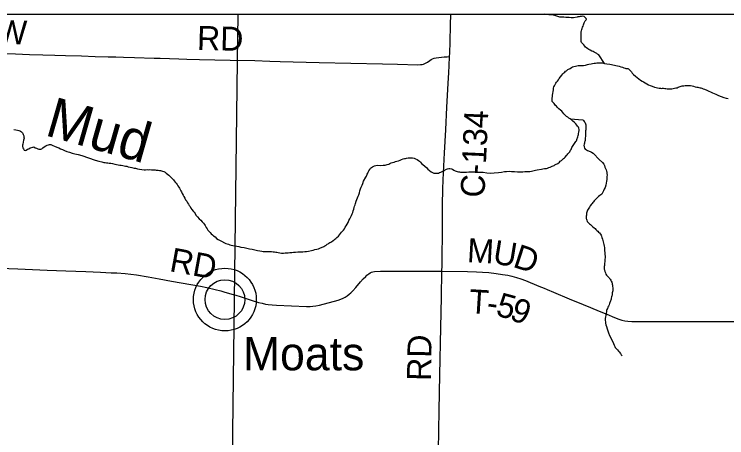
# Model space of a CAD drawing. Extents: x 2.1 to 73.9, y 4 to 26.
# Drawn here: x 44.65 to 45.494, y 24.403 to 24.905 of the extents above; entities that cross this region are included whole.
import ezdxf

# ---------------------------------------------------------------- set-up
doc = ezdxf.new("R2010")
doc.units = 0
for name, color, linetype in [('GM_X_County_Road', 7, 'Continuous'), ('GM_X_County_Road_Text', 7, 'Continuous'), ('GM_X_Minor_River', 7, 'Continuous'), ('GM_X_Minor_River_Text', 7, 'Continuous'), ('GM_X_Rail_Line', 7, 'Continuous'), ('GM_X_Township_Road', 7, 'Continuous'), ('GM_X_Township_Road_Text', 7, 'Continuous'), ('GM_X_Unincorporated', 7, 'Continuous'), ('GM_X_Unincorporated_Location', 7, 'Continuous'), ('GM_X_Unincorporated_Text', 7, 'Continuous'), ('SH_Data', 7, 'Continuous')]:
    doc.layers.add(name, color=color, linetype=linetype)

msp = doc.modelspace()

# ---------------------------------------------------------------- linework, layer by layer
at = {"layer": 'GM_X_County_Road'}
msp.add_line((45.16551, 24.84401), (45.16606, 24.85491), dxfattribs=at)
for points in [[(45.16606, 24.85491), (45.16626, 24.85886), (45.1666, 24.87222), (45.16722, 24.89212), (45.16754, 24.90511)], [(45.15687, 24.6007), (45.15704, 24.60732), (45.15719, 24.62068), (45.15741, 24.64213), (45.1576, 24.66451), (45.15768, 24.67881), (45.15796, 24.69807), (45.15826, 24.70846), (45.1589, 24.71731), (45.16008, 24.7409), (45.1615, 24.76822), (45.16283, 24.79492), (45.16439, 24.82285), (45.16511, 24.8362), (45.16551, 24.84401)], [(44.63313, 24.60432), (44.65487, 24.6033), (44.68929, 24.60188), (44.71164, 24.60095), (44.73522, 24.6001), (44.75263, 24.59946), (44.76535, 24.5988), (44.77187, 24.59851), (44.7818, 24.59776), (44.78831, 24.59704), (44.79508, 24.59605), (44.80888, 24.59374), (44.82205, 24.59143), (44.83673, 24.5888), (44.87101, 24.58265), (44.87863, 24.58106), (44.88827, 24.57875), (44.89496, 24.57715), (44.89999, 24.57584), (44.90984, 24.57298), (44.91268, 24.57211)], [(44.91268, 24.57211), (44.91788, 24.5705), (44.93107, 24.56625), (44.93965, 24.56359), (44.94384, 24.56248), (44.94806, 24.56154), (44.9511, 24.56105), (44.95571, 24.5606), (44.96097, 24.56029), (44.99668, 24.55882), (45.00068, 24.55887), (45.00407, 24.55908), (45.00774, 24.55956), (45.01199, 24.56037), (45.03384, 24.56632), (45.03733, 24.56755), (45.03988, 24.56862), (45.04233, 24.56989), (45.04465, 24.57137), (45.04708, 24.57323), (45.04915, 24.57507), (45.05131, 24.57726), (45.05479, 24.58122), (45.06046, 24.58782), (45.06381, 24.59152), (45.0666, 24.59446), (45.06797, 24.59578), (45.07023, 24.59747), (45.07183, 24.59852), (45.07356, 24.59937), (45.07509, 24.59988), (45.07698, 24.60022), (45.08417, 24.6006), (45.09413, 24.60064), (45.10656, 24.60053), (45.15687, 24.6007)], [(45.15193, 24.34944), (45.15216, 24.36148), (45.15276, 24.38821), (45.15376, 24.43545), (45.15451, 24.47771), (45.15565, 24.53366), (45.15644, 24.5697), (45.15687, 24.6007)]]:
    msp.add_lwpolyline(points, dxfattribs=at)
at = {"layer": 'GM_X_Minor_River'}
for points in [[(45.34948, 24.84681), (45.3426, 24.85718), (45.34129, 24.85796), (45.34016, 24.85874), (45.33884, 24.85952), (45.33714, 24.86031), (45.33582, 24.8609), (45.3343, 24.86149), (45.33261, 24.86247), (45.33072, 24.86345), (45.32959, 24.86423), (45.32809, 24.8652), (45.32696, 24.86617), (45.32603, 24.86732), (45.3251, 24.86867), (45.32417, 24.86982), (45.32229, 24.87156), (45.32193, 24.87271), (45.32195, 24.87404), (45.32178, 24.87556), (45.32181, 24.87746), (45.32165, 24.87918), (45.32168, 24.88107), (45.32171, 24.88316), (45.32173, 24.88449), (45.32213, 24.88563), (45.32253, 24.88695), (45.32293, 24.88809), (45.32333, 24.8896), (45.32412, 24.89111), (45.32471, 24.89243), (45.32511, 24.89375), (45.32551, 24.89489), (45.32572, 24.89583), (45.32669, 24.89715), (45.32746, 24.89808), (45.32824, 24.89902), (45.32787, 24.89998), (45.32656, 24.90133), (45.32525, 24.90249), (45.32373, 24.90289), (45.32221, 24.90254), (45.32068, 24.90237), (45.31935, 24.90201), (45.31801, 24.90185), (45.31687, 24.90148), (45.31267, 24.90098), (45.31134, 24.901), (45.30982, 24.90103), (45.30773, 24.90125), (45.30583, 24.90128), (45.30374, 24.90131), (45.30146, 24.90154), (45.29975, 24.90157), (45.29804, 24.90159), (45.29671, 24.9018), (45.29538, 24.90202), (45.29425, 24.90241), (45.29311, 24.90281), (45.29198, 24.90321), (45.29046, 24.90361), (45.28914, 24.90402), (45.28781, 24.90423), (45.28648, 24.90444), (45.28515, 24.90446), (45.28401, 24.90448), (45.28306, 24.90468), (45.28211, 24.90489), (45.28097, 24.9049), (45.28002, 24.90492), (45.27896, 24.90511)], [(45.30427, 24.83822), (45.306, 24.83952), (45.30696, 24.84007), (45.30792, 24.84044), (45.30888, 24.84099), (45.31022, 24.84192), (45.31156, 24.84266), (45.31328, 24.8432), (45.31519, 24.84355), (45.31672, 24.84391), (45.31844, 24.84426), (45.32053, 24.84423), (45.32262, 24.84439), (45.32472, 24.84454), (45.327, 24.84489), (45.32911, 24.84542), (45.33102, 24.84596), (45.33349, 24.8463), (45.33521, 24.84666), (45.33712, 24.84701), (45.33883, 24.84717), (45.34036, 24.84734), (45.34188, 24.84769), (45.34341, 24.84767), (45.34512, 24.84764), (45.34721, 24.84742), (45.34948, 24.84681), (45.35213, 24.8462), (45.35555, 24.84576), (45.35764, 24.84554), (45.36276, 24.84451), (45.36484, 24.84391), (45.36692, 24.84349), (45.36882, 24.84289), (45.37071, 24.84229), (45.37241, 24.8417), (45.37393, 24.84129), (45.37487, 24.8409), (45.37582, 24.84069), (45.37696, 24.84067), (45.3779, 24.84028), (45.37922, 24.83912), (45.38052, 24.83757), (45.38146, 24.8368), (45.38239, 24.83546), (45.38388, 24.83353), (45.38614, 24.83179), (45.3882, 24.83004), (45.39027, 24.82849), (45.39215, 24.82713), (45.39385, 24.82596), (45.39554, 24.8248), (45.39742, 24.82363), (45.3995, 24.82245), (45.40157, 24.82147), (45.40365, 24.82068), (45.40573, 24.81969), (45.40876, 24.8187), (45.41065, 24.81828), (45.41236, 24.81807), (45.41407, 24.81766), (45.41558, 24.81745), (45.41691, 24.81724), (45.41805, 24.81741), (45.4192, 24.81739), (45.42071, 24.81718), (45.42223, 24.81696), (45.42375, 24.81675), (45.42527, 24.81672), (45.42755, 24.81669), (45.42927, 24.81685), (45.43404, 24.81772), (45.43537, 24.81808), (45.43652, 24.81863), (45.43786, 24.81918), (45.43901, 24.81954), (45.44016, 24.81991), (45.44149, 24.82008), (45.4434, 24.82043), (45.44492, 24.82059), (45.44663, 24.82056), (45.44816, 24.82073), (45.44949, 24.82071), (45.4512, 24.82049), (45.4531, 24.82027), (45.45499, 24.81986), (45.45688, 24.81926), (45.45859, 24.81885), (45.45992, 24.81864), (45.46124, 24.81824), (45.46257, 24.81803), (45.46352, 24.81782), (45.46484, 24.81742), (45.46635, 24.81683), (45.46787, 24.81624), (45.46881, 24.81584), (45.46995, 24.81544), (45.47146, 24.81485), (45.47316, 24.81406), (45.47505, 24.81327), (45.47731, 24.8121)], [(45.26302, 24.71916), (45.26455, 24.71952), (45.26607, 24.71987), (45.26779, 24.72042), (45.26951, 24.72077), (45.27485, 24.72164), (45.27638, 24.72199), (45.27828, 24.72215), (45.28057, 24.7223), (45.2821, 24.72285), (45.28363, 24.7234), (45.28516, 24.72394), (45.2865, 24.72449), (45.28765, 24.72504), (45.28879, 24.7254), (45.28975, 24.72596), (45.29071, 24.72651), (45.29225, 24.72744), (45.29321, 24.7278), (45.29436, 24.72836), (45.29609, 24.72985), (45.29687, 24.73098), (45.29841, 24.7319), (45.29975, 24.73283), (45.30091, 24.73395), (45.30207, 24.73507), (45.30303, 24.73582), (45.30439, 24.7377), (45.30536, 24.73863), (45.30614, 24.73957), (45.30691, 24.74051), (45.30827, 24.7422), (45.30925, 24.74389), (45.30983, 24.74483), (45.31023, 24.74596), (45.31082, 24.74709), (45.3116, 24.74841), (45.31219, 24.74973), (45.31297, 24.75086), (45.31394, 24.75199), (45.31471, 24.75292), (45.31531, 24.75424), (45.31608, 24.75518), (45.31707, 24.75764), (45.31747, 24.75877), (45.31787, 24.7599), (45.31808, 24.76142), (45.31848, 24.76255), (45.31869, 24.76388), (45.31909, 24.76521), (45.31911, 24.76616), (45.31931, 24.7671), (45.31933, 24.76843), (45.31898, 24.77015), (45.31862, 24.77129), (45.31731, 24.77264), (45.31657, 24.7738), (45.31544, 24.77514), (45.31395, 24.77669), (45.31207, 24.77843), (45.31019, 24.77979), (45.30869, 24.78095), (45.30738, 24.78211), (45.30587, 24.78309), (45.30455, 24.78406), (45.30324, 24.78522), (45.3023, 24.78599), (45.30137, 24.78715), (45.30025, 24.7885), (45.29894, 24.79004), (45.29725, 24.79139), (45.29537, 24.79294), (45.29388, 24.79468), (45.29257, 24.79603), (45.29144, 24.797), (45.2907, 24.79815), (45.28977, 24.79949), (45.28865, 24.80046), (45.28753, 24.80181), (45.28754, 24.80295), (45.28737, 24.80409), (45.28802, 24.80902), (45.28824, 24.81111), (45.28847, 24.81358), (45.28889, 24.81566), (45.28911, 24.81756), (45.28951, 24.81907), (45.2901, 24.82039), (45.29089, 24.8219), (45.29167, 24.82322), (45.29264, 24.82453), (45.29361, 24.82584), (45.29478, 24.82754), (45.29594, 24.82904), (45.29731, 24.83111), (45.29905, 24.83279), (45.30021, 24.83448), (45.30137, 24.8356), (45.30234, 24.83654), (45.3033, 24.83747), (45.30427, 24.83822)], [(45.47731, 24.8121), (45.48128, 24.81032), (45.48449, 24.80894), (45.48751, 24.80756), (45.49073, 24.80637), (45.49357, 24.80576), (45.49584, 24.80515)], [(45.30869, 24.78095), (45.3237, 24.77995), (45.32464, 24.77918), (45.32538, 24.77803), (45.32632, 24.77706), (45.32686, 24.77534), (45.32722, 24.7742), (45.32739, 24.77305), (45.32737, 24.77172), (45.32732, 24.76811), (45.3271, 24.76679), (45.32708, 24.76527), (45.32706, 24.76375), (45.32704, 24.76242), (45.32681, 24.76014), (45.32659, 24.75844), (45.32657, 24.75673), (45.32635, 24.7554), (45.32596, 24.75427), (45.32575, 24.75332), (45.32555, 24.75237), (45.32533, 24.75104), (45.32512, 24.74972), (45.3253, 24.74877), (45.32528, 24.74782), (45.32583, 24.74629), (45.32658, 24.74532), (45.32808, 24.74435), (45.32921, 24.74376), (45.33035, 24.74336), (45.33129, 24.74297), (45.33262, 24.74238), (45.33413, 24.74178), (45.33582, 24.74062), (45.33713, 24.73946), (45.33825, 24.73811), (45.33938, 24.73695), (45.34012, 24.73599), (45.34162, 24.73463), (45.34312, 24.73309), (45.34725, 24.72941), (45.34874, 24.72749), (45.34928, 24.72577), (45.35001, 24.72405), (45.35075, 24.72214), (45.35129, 24.72061), (45.35184, 24.71927), (45.35202, 24.71832), (45.35238, 24.71736), (45.35236, 24.71622), (45.35253, 24.71451), (45.35231, 24.71299), (45.35229, 24.71128), (45.35207, 24.70939), (45.35165, 24.70711), (45.35123, 24.70484), (45.35082, 24.70257), (45.35021, 24.69992), (45.34922, 24.69765), (45.34843, 24.69595), (45.34764, 24.69426), (45.34609, 24.692), (45.34378, 24.69033), (45.34223, 24.68902), (45.34127, 24.68809), (45.3403, 24.68696), (45.33914, 24.68584), (45.33798, 24.68472), (45.33702, 24.68378), (45.33643, 24.68284), (45.33547, 24.68191), (45.33469, 24.68097), (45.33391, 24.68003), (45.33255, 24.67816), (45.33158, 24.67646), (45.33079, 24.67514), (45.33002, 24.67402), (45.32943, 24.67288), (45.32884, 24.67156), (45.32844, 24.67062), (45.32823, 24.66948), (45.32802, 24.66835), (45.328, 24.66702), (45.32779, 24.66569), (45.32777, 24.66417), (45.32775, 24.66303), (45.32812, 24.66208), (45.32848, 24.66093), (45.32903, 24.65959), (45.33164, 24.6567), (45.33277, 24.65573), (45.3339, 24.65476), (45.33483, 24.65399), (45.33577, 24.65321), (45.33709, 24.65205), (45.33821, 24.65108), (45.33934, 24.65012)], [(44.65004, 24.76863), (44.65231, 24.76822), (44.65421, 24.76781), (44.65573, 24.7674), (44.65686, 24.76701), (44.65799, 24.76642), (44.65912, 24.76583), (44.66006, 24.76467), (44.66042, 24.76372), (44.66098, 24.76276), (44.66171, 24.76104), (44.66188, 24.75952), (44.66205, 24.75818), (44.66184, 24.75723), (44.66144, 24.75591), (44.66041, 24.75099), (44.66039, 24.74985), (44.66037, 24.74852), (44.66054, 24.74681), (44.66128, 24.74546), (44.66201, 24.74412), (44.66353, 24.74353), (44.66449, 24.74408), (44.66622, 24.7452), (44.66756, 24.74574), (44.66928, 24.74667), (44.67081, 24.74721), (44.67253, 24.74775), (44.67349, 24.74793), (44.67518, 24.74695), (44.6767, 24.74636), (44.67839, 24.74557), (44.67972, 24.74536), (44.68086, 24.74515), (44.682, 24.74513), (44.68315, 24.74569), (44.68412, 24.74681), (44.68604, 24.74792), (44.68796, 24.74903), (44.68949, 24.74976), (44.69103, 24.7505), (44.69236, 24.75086), (44.69369, 24.75065), (44.69464, 24.75025), (44.69614, 24.74947), (44.69804, 24.74887), (44.70087, 24.74749), (44.70314, 24.7467), (44.7054, 24.74571), (44.70767, 24.74472)], [(44.70767, 24.74472), (44.70994, 24.74355), (44.71258, 24.74256), (44.7158, 24.74155), (44.71883, 24.74056), (44.72205, 24.73955), (44.72603, 24.73873), (44.73038, 24.73752), (44.74628, 24.73233), (44.75044, 24.73112), (44.75404, 24.73011), (44.7565, 24.7295), (44.75821, 24.72929), (44.75973, 24.72907), (44.76125, 24.72886), (44.76296, 24.72864), (44.76466, 24.72842), (44.76675, 24.72801), (44.76959, 24.7274), (44.77168, 24.72698), (44.77357, 24.72657), (44.77547, 24.72635), (44.77718, 24.72613), (44.77908, 24.72572), (44.78078, 24.72532), (44.7823, 24.7251), (44.78382, 24.72489), (44.78552, 24.72429), (44.7876, 24.72369), (44.78988, 24.72327), (44.79234, 24.72285), (44.79386, 24.72264), (44.79633, 24.72203), (44.79879, 24.72142), (44.80145, 24.72119), (44.8041, 24.72077), (44.80601, 24.72073), (44.80772, 24.7209), (44.80943, 24.72087), (44.81114, 24.72103), (44.81304, 24.72081), (44.81532, 24.72078), (44.81722, 24.72056), (44.81855, 24.72035), (44.82007, 24.72032), (44.82102, 24.72012), (44.82235, 24.72009), (44.82349, 24.71989), (44.82463, 24.71968), (44.82614, 24.71927), (44.82765, 24.71868), (44.82897, 24.7179), (44.83029, 24.71674), (44.83367, 24.71421), (44.8348, 24.71325), (44.8361, 24.7117), (44.83741, 24.71035), (44.83891, 24.709), (44.83984, 24.70766), (44.84096, 24.70612), (44.84227, 24.70477), (44.8432, 24.70323), (44.84431, 24.70169), (44.84524, 24.70016), (44.84617, 24.69881), (44.8471, 24.69728), (44.84784, 24.69594), (44.84858, 24.6946), (44.8493, 24.69249), (44.85042, 24.69077), (44.85134, 24.68904), (44.85246, 24.68731), (44.85337, 24.68521), (44.85468, 24.68348), (44.85579, 24.68175), (44.85671, 24.68003), (44.85764, 24.67849), (44.85876, 24.67714), (44.85969, 24.67542), (44.8608, 24.67369), (44.86229, 24.67177), (44.86341, 24.67042), (44.86453, 24.66888), (44.86564, 24.66696), (44.86732, 24.66504), (44.86937, 24.66272), (44.87144, 24.66098), (44.87312, 24.65924), (44.87462, 24.65751), (44.87574, 24.65597), (44.87666, 24.65463), (44.87758, 24.65252), (44.87889, 24.65079), (44.87981, 24.64907), (44.88112, 24.64772), (44.88243, 24.64637), (44.88374, 24.64483), (44.88505, 24.64366), (44.88655, 24.6425), (44.88824, 24.64114), (44.89012, 24.6394)], [(45.06308, 24.70448), (45.06389, 24.70713), (45.06681, 24.71183), (45.0674, 24.71315), (45.06799, 24.71428), (45.06839, 24.71542), (45.06898, 24.71674), (45.06938, 24.71787), (45.07017, 24.71957), (45.07153, 24.72126), (45.0725, 24.72257), (45.07346, 24.72351), (45.07481, 24.72425), (45.07711, 24.72535), (45.07882, 24.7257), (45.08111, 24.72624), (45.08377, 24.726), (45.08739, 24.72614), (45.08986, 24.72629), (45.09197, 24.72701), (45.09388, 24.72755), (45.09541, 24.7281), (45.09675, 24.72884), (45.09828, 24.72938), (45.10019, 24.72992), (45.1021, 24.73046), (45.10363, 24.73101), (45.10535, 24.73155), (45.10746, 24.73228), (45.10918, 24.73301), (45.1109, 24.73355), (45.11243, 24.7341), (45.11376, 24.73427), (45.1151, 24.73462), (45.11682, 24.73479), (45.11853, 24.73495), (45.12024, 24.73492), (45.12195, 24.7349), (45.12385, 24.73449), (45.12555, 24.73389), (45.12763, 24.73291), (45.12913, 24.73174), (45.13026, 24.73077), (45.13157, 24.72961), (45.13288, 24.72826), (45.13438, 24.72691), (45.13888, 24.72304), (45.14038, 24.7213), (45.14207, 24.71995), (45.14413, 24.7182), (45.14564, 24.71742), (45.14715, 24.71682), (45.14867, 24.71661), (45.14982, 24.71678), (45.15115, 24.71676), (45.15267, 24.71693), (45.1542, 24.71747), (45.15554, 24.71802), (45.15707, 24.71857), (45.15822, 24.71893), (45.15976, 24.72004), (45.16072, 24.7206), (45.16225, 24.72134), (45.16359, 24.72188), (45.16493, 24.72224), (45.16645, 24.72241), (45.16834, 24.72181), (45.16948, 24.72141), (45.17117, 24.72043), (45.17268, 24.71946), (45.17476, 24.71867), (45.17666, 24.71845), (45.1778, 24.71824), (45.17874, 24.71803), (45.17989, 24.71801), (45.18178, 24.71779), (45.18349, 24.71777), (45.18597, 24.71811), (45.18883, 24.71844), (45.19225, 24.71839), (45.19568, 24.71833), (45.1991, 24.71809), (45.20233, 24.71804), (45.20575, 24.71779), (45.20992, 24.71716), (45.21429, 24.7169), (45.21867, 24.71721), (45.224, 24.7175), (45.22762, 24.71802), (45.23087, 24.71853), (45.23353, 24.71887), (45.23658, 24.71901), (45.23943, 24.71878), (45.24285, 24.71872), (45.24627, 24.71848), (45.24969, 24.71823), (45.25274, 24.71838), (45.25521, 24.71872), (45.25864, 24.71885), (45.26092, 24.71882), (45.26302, 24.71916)], [(44.89012, 24.6394), (44.892, 24.63804), (44.89426, 24.63687), (44.90105, 24.63334), (44.90257, 24.63294), (44.90408, 24.63253), (44.9056, 24.63194), (44.9073, 24.63153), (44.90919, 24.63093), (44.91166, 24.63051), (44.91394, 24.63009), (44.9164, 24.62967), (44.91887, 24.62907), (44.92266, 24.62862), (44.92589, 24.628), (44.92911, 24.62719), (44.93233, 24.62657), (44.93536, 24.62576), (44.93839, 24.62514), (44.94124, 24.62472), (44.94352, 24.6243), (44.94522, 24.62409), (44.94674, 24.62406), (44.94845, 24.62384), (44.95073, 24.62381), (44.95283, 24.62396), (44.95511, 24.62393), (44.9572, 24.6237), (44.95872, 24.62349), (44.96005, 24.62328), (44.96137, 24.62307), (44.96289, 24.62266), (44.96478, 24.62225), (44.96706, 24.62203), (44.96916, 24.622), (44.97125, 24.62234), (44.97467, 24.62229), (44.97677, 24.62263), (44.97906, 24.62279), (44.98115, 24.62294), (44.98344, 24.62329), (44.98611, 24.62343), (44.98896, 24.62358), (44.992, 24.62353), (44.99448, 24.62387), (44.99657, 24.62403), (44.99886, 24.62437), (45.00229, 24.62489), (45.00459, 24.62542), (45.0065, 24.62615), (45.00879, 24.62668), (45.0107, 24.62722), (45.01242, 24.62796), (45.01702, 24.62978), (45.01836, 24.63052), (45.01971, 24.63145), (45.02087, 24.63257), (45.02201, 24.63312), (45.02297, 24.63368), (45.02413, 24.63442), (45.02528, 24.63497), (45.02624, 24.63553), (45.02797, 24.63702), (45.02912, 24.63776), (45.03009, 24.6385), (45.03124, 24.63944), (45.0324, 24.64056), (45.03433, 24.64224), (45.03569, 24.64374), (45.03685, 24.64543), (45.03802, 24.64674), (45.03918, 24.64805), (45.04034, 24.64936), (45.04151, 24.65086), (45.04248, 24.65256), (45.04346, 24.65444), (45.04482, 24.65632), (45.0458, 24.6582), (45.0468, 24.66066), (45.04797, 24.66273), (45.04895, 24.6648), (45.04974, 24.6665), (45.05053, 24.66839), (45.05132, 24.67028), (45.05192, 24.67198), (45.05252, 24.67406), (45.05293, 24.67595), (45.05353, 24.67746), (45.05412, 24.67916), (45.05472, 24.68086), (45.05552, 24.68351), (45.05613, 24.68559), (45.05692, 24.68748), (45.05752, 24.68937), (45.0585, 24.69125), (45.0591, 24.69333), (45.05971, 24.69579), (45.06051, 24.69806), (45.06131, 24.70033), (45.06229, 24.70259), (45.06308, 24.70448)], [(45.33934, 24.65012), (45.34046, 24.64896), (45.34159, 24.64799), (45.34252, 24.64684), (45.34346, 24.64606), (45.34476, 24.64433), (45.34551, 24.64318), (45.34606, 24.64203), (45.34641, 24.64031), (45.34714, 24.63859), (45.3475, 24.63707), (45.34804, 24.63535), (45.3484, 24.63363), (45.34875, 24.63211), (45.34892, 24.63039), (45.34927, 24.62849), (45.34943, 24.62678), (45.34959, 24.62468), (45.34994, 24.62278), (45.3499, 24.62069), (45.35005, 24.61802), (45.35003, 24.61632), (45.35, 24.6148), (45.34979, 24.61347), (45.34976, 24.61176), (45.34955, 24.61024), (45.34953, 24.60872), (45.34931, 24.60721), (45.3491, 24.60607), (45.34909, 24.60512), (45.34905, 24.60303), (45.34942, 24.60207), (45.34996, 24.60036), (45.35014, 24.5994), (45.3505, 24.59845), (45.35105, 24.59692), (45.35198, 24.59576), (45.35479, 24.59287), (45.35554, 24.59191), (45.35609, 24.59095), (45.35684, 24.58999), (45.35739, 24.58884), (45.35794, 24.5875), (45.35849, 24.58635), (45.35866, 24.58502), (45.35883, 24.58387), (45.359, 24.58254), (45.35917, 24.58102), (45.35915, 24.57988), (45.35913, 24.57874), (45.35911, 24.57741), (45.3589, 24.57627), (45.35869, 24.57495), (45.35848, 24.57362), (45.35846, 24.57229), (45.35806, 24.57116), (45.35785, 24.57002), (45.35745, 24.5687), (45.35724, 24.56756), (45.35684, 24.56624), (45.35645, 24.56529), (45.35624, 24.56435), (45.35585, 24.5634), (45.35545, 24.56227), (45.35485, 24.56076), (45.35407, 24.55925), (45.35348, 24.55793), (45.35288, 24.55642), (45.35229, 24.5551), (45.35189, 24.55396), (45.35167, 24.55226), (45.35127, 24.55093), (45.35106, 24.54961), (45.35085, 24.5479), (45.35063, 24.54639), (45.35041, 24.54468), (45.35039, 24.54335), (45.35037, 24.54202), (45.35054, 24.5405), (45.3507, 24.53897), (45.35105, 24.53707), (45.35178, 24.53497), (45.3525, 24.5323), (45.35323, 24.53), (45.35413, 24.52733), (45.35542, 24.52427), (45.3569, 24.52159), (45.36002, 24.51489), (45.36075, 24.51297), (45.36168, 24.51125), (45.36223, 24.5101), (45.36316, 24.50895), (45.36466, 24.5074), (45.36616, 24.50586), (45.3669, 24.5049), (45.36821, 24.50317), (45.36876, 24.50221), (45.36932, 24.50125), (45.37025, 24.50009), (45.37025, 24.50028), (45.37025, 24.50009)]]:
    msp.add_lwpolyline(points, dxfattribs=at)
at = {"layer": 'GM_X_Rail_Line'}
msp.add_lwpolyline([(44.25279, 22.99625), (44.25498, 23.0348), (44.25803, 23.06783), (44.26715, 23.10087), (44.27758, 23.12043), (44.29583, 23.15563), (44.31538, 23.18258), (44.3471, 23.21431), (44.40098, 23.26169), (44.50613, 23.35296), (44.6569, 23.48292), (44.79159, 23.59898), (44.81114, 23.61506), (44.82896, 23.63201), (44.85329, 23.66244), (44.87458, 23.69938), (44.89022, 23.7372), (44.89935, 23.77414), (44.90326, 23.82108), (44.90369, 23.8489), (44.9076, 24.16793), (44.90847, 24.34745), (44.91499, 24.84946), (44.91547, 24.90511)], dxfattribs=at)
at = {"layer": 'GM_X_Township_Road'}
for points in [[(44.63129, 24.8585), (44.65186, 24.85803), (44.6683, 24.85746), (44.68418, 24.85698), (44.69847, 24.85657), (44.71121, 24.85613), (44.7302, 24.85567), (44.74619, 24.85514), (44.76153, 24.85475), (44.77074, 24.85456), (44.77965, 24.85431), (44.79301, 24.85384), (44.816, 24.85309), (44.82337, 24.85302), (44.84538, 24.85229), (44.8547, 24.85204), (44.86993, 24.85166), (44.90629, 24.85078), (44.9355, 24.85009), (44.95321, 24.84954), (44.96533, 24.84917), (45.01163, 24.8478), (45.08654, 24.84621), (45.10426, 24.84582), (45.12851, 24.84525), (45.13163, 24.84536), (45.13307, 24.84555)], [(45.13307, 24.84555), (45.13342, 24.84561), (45.13528, 24.84602), (45.13758, 24.84695), (45.13995, 24.84843), (45.14273, 24.85043), (45.14404, 24.85127), (45.14568, 24.85215), (45.14771, 24.85293), (45.15012, 24.85352), (45.1532, 24.85398), (45.15939, 24.85449), (45.16312, 24.85473), (45.16606, 24.85491)], [(45.15687, 24.6007), (45.18712, 24.60015), (45.19801, 24.59988), (45.20485, 24.59953), (45.21261, 24.59891), (45.22096, 24.59795), (45.22867, 24.59683), (45.23481, 24.59573), (45.23967, 24.59464), (45.24541, 24.59312), (45.25016, 24.59159), (45.25599, 24.58939), (45.27176, 24.58277), (45.27779, 24.58035), (45.28158, 24.57893), (45.28898, 24.57567), (45.30763, 24.56792), (45.32401, 24.56117), (45.33294, 24.55754), (45.34328, 24.55324), (45.35216, 24.54951), (45.36135, 24.54573), (45.36657, 24.54377), (45.3701, 24.54268), (45.37369, 24.54185), (45.37704, 24.54138), (45.38197, 24.54104), (45.38693, 24.54088), (45.395, 24.54087), (45.41614, 24.54097), (45.44256, 24.54099), (45.4609, 24.54102), (45.47675, 24.54102), (45.50348, 24.54103)]]:
    msp.add_lwpolyline(points, dxfattribs=at)
at = {"layer": 'GM_X_Unincorporated'}
for radius in [0.0372, 0.02358]:
    msp.add_circle((44.89991, 24.56693), radius, dxfattribs=at)
at = {"layer": 'GM_X_Unincorporated_Location'}
msp.add_line((44.89991, 24.56693), (44.89991, 24.56693), dxfattribs=at)
at = {"layer": 'SH_Data'}
msp.add_line((41.95853, 24.90511), (48.75853, 24.90511), dxfattribs=at)

# ---------------------------------------------------------------- texts
at = {"layer": 'GM_X_County_Road_Text'}
for s, rotation, p in [('C-134', 87.36166, (45.20719, 24.6873)), ('RD', 349.5626, (44.83324, 24.60075)), ('RD', 89.01278, (45.14389, 24.47036))]:
    msp.add_text(s, height=0.028409, rotation=rotation, dxfattribs=at).set_placement(p)
at = {"layer": 'GM_X_Minor_River_Text'}
msp.add_text('Mud', height=0.047375, rotation=344.04521, dxfattribs=at).set_placement((44.68539, 24.76208))
at = {"layer": 'GM_X_Township_Road_Text'}
for s, height, rotation, p in [('BRADSHAW', 0.028409, 358.33205, (44.44583, 24.87551)), ('RD', 0.028409, 358.5108, (44.8666, 24.863)), ('M', 0.02841, 356.94157, (45.1862, 24.61134)), ('U', 0.02841, 350.7398, (45.21618, 24.60979)), ('D', 0.02841, 341.87493, (45.23973, 24.60604)), ('T', 0.02841, 356.48783, (45.1883, 24.55095)), ('5', 0.02841, 344.89025, (45.21956, 24.54829)), ('9', 0.02841, 338.17057, (45.23562, 24.544)), ('-', 0.02841, 352.09123, (45.20893, 24.5497))]:
    msp.add_text(s, height=height, rotation=rotation, dxfattribs=at).set_placement(p)
at = {"layer": 'GM_X_Unincorporated_Text'}
msp.add_text('Moats', height=0.039489, rotation=0.00001, dxfattribs=at).set_placement((44.92121, 24.48307))

doc.saveas('drawing.dxf')
